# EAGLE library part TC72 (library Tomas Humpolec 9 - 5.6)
Digital Temperature Sensor with SPI Interface Features Temperature-to-Digital Converter SPI Compatible Interface 10-Bit Resolution (0.25°C/Bit) ±2°C (max.) Accuracy from -40°C to +85°C ±3°C (max.) Accuracy from -55°C to +125°C 2.65V to 5.5V Operating Range Low Power Consumption: - 250 yA Continuous Temperature Conversion Mode - 1 yA (max.) Shutdown Mode Power Saving One-Shot Temperature Measurement Industry Standard 8-Pin MSOP Package Space Saving 8-Pin DFN (3x3 mm) Package Typical Applications Personal Computers and Servers Hard Disk Drives and Other PC Peripherals Entertainment Systems Office Equipment Datacom Equipment Mobile Phones General Purpose Temperature Monitoring
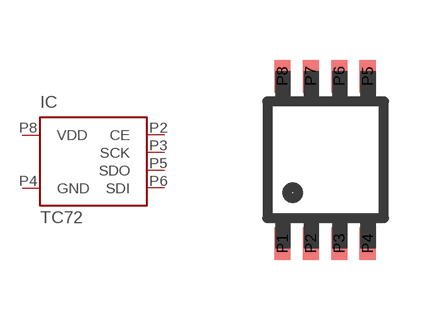
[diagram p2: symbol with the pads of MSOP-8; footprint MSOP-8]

Designator prefix IC

## TC72  [MSOP-8]
P2  CE
P3  SCK
P4  GND  pwr
P5  SDO
P6  SDI
P8  VDD  pwr

## Footprint MSOP-8 (pad centres in mm)
Small Outline Package SO-8, CASE 751
smd 0.406 x 0.813: P1 -2.159,-2.54; P2 -1.448,-2.54; P3 -0.737,-2.54; P4 -0.025,-2.54; P5 -0.025,1.651; P6 -0.737,1.651; P7 -1.448,1.651; P8 -2.159,1.651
